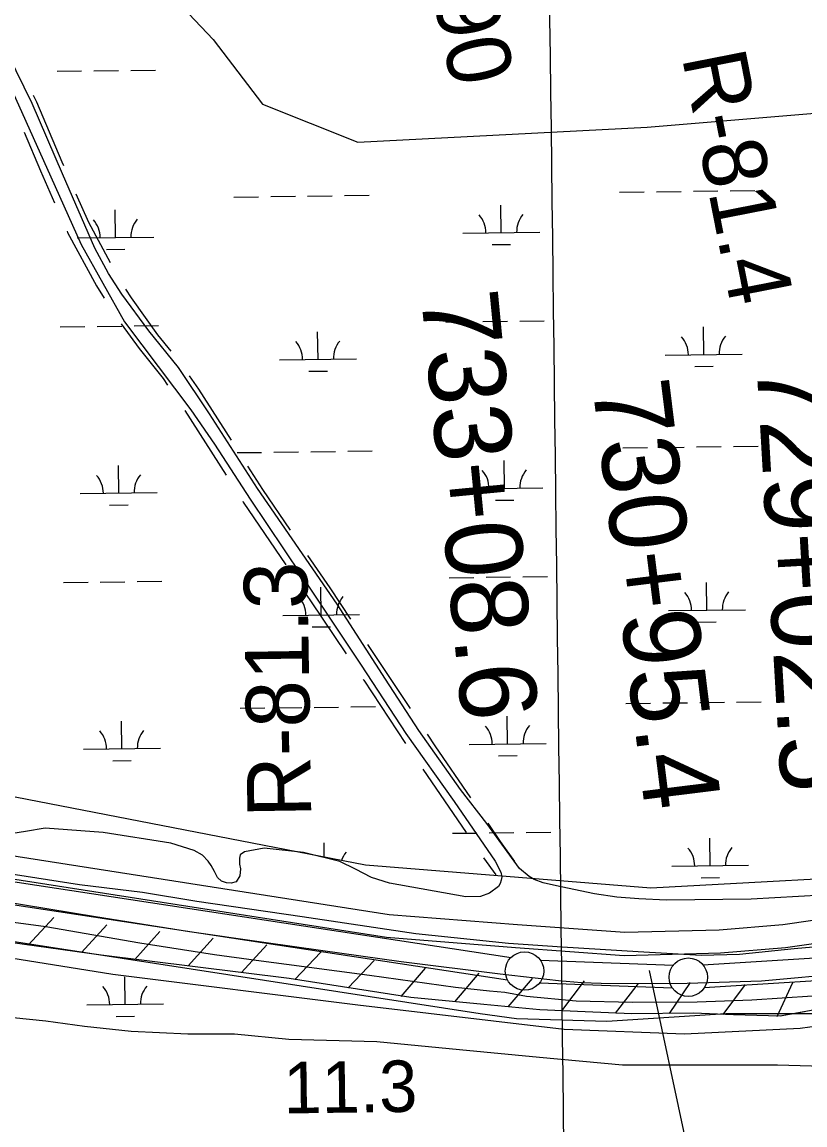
# Model space of a CAD drawing. Extents: x 3715084 to 3753216, y 488173 to 513963.
# Drawn here: x 3729121 to 3730139, y 501088 to 502523 of the extents above; entities that cross this region are included whole.
import ezdxf

# ---------------------------------------------------------------- set-up
doc = ezdxf.new("R2010")
doc.units = 0
for name, color, linetype in [('V-FLOD-BASE', 7, 'Continuous'), ('V-GRID-MAJR', 7, 'Continuous'), ('V-LEVE-TOET', 7, 'Continuous'), ('V-RIVR-RANG', 7, 'Continuous'), ('V-RIVR-RANG-IDEN', 7, 'Continuous'), ('V-ROAD-CNTR', 7, 'Continuous'), ('V-RRAP-FSHR', 7, 'Continuous'), ('V-SITE-VEGE', 7, 'Continuous'), ('V-SURV-IDEN', 7, 'Continuous'), ('V-SURV-LINE', 7, 'Continuous'), ('V-WETL-SWMP', 7, 'Continuous')]:
    doc.layers.add(name, color=color, linetype=linetype)

msp = doc.modelspace()

# ---------------------------------------------------------------- linework, layer by layer
at = {"layer": 'V-FLOD-BASE'}
msp.add_lwpolyline([(3728101.8570000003, 501532.90400000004), (3728267.9250000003, 501507.679), (3728417.988, 501485.28), (3728525.819, 501467.973), (3728627.609, 501453.266), (3728731.631, 501437.386), (3728842.612, 501418.911), (3728945.323, 501403.42), (3729092.378, 501379.042), (3729216.214, 501358.908), (3729338.343, 501339.293), (3729435.279, 501325.61600000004), (3729508.865, 501315.132), (3729613.8030000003, 501300.30700000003), (3729742.866, 501284.386), (3729818.546, 501275.483), (3729848.7090000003, 501272.97000000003), (3729874.147, 501271.88300000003), (3729921.4760000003, 501271.53), (3729985.978, 501272.026), (3730082.981, 501275.264), (3730197.006, 501285.379)], dxfattribs=at)
at = {"layer": 'V-GRID-MAJR'}
msp.add_spline([(3729916.433, 493722.87), (3729841.541, 499780.245), (3729766.611, 505840.705), (3729691.682, 511901.17600000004), (3729691.644, 511904.24700000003)], degree=3, dxfattribs=at)
at = {"layer": 'V-LEVE-TOET'}
for points in [[(3728035.076, 501579.658), (3728225.339, 501552.42600000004), (3728426.043, 501520.704), (3728505.335, 501509.389), (3728525.404, 501506.905), (3728559.646, 501499.753), (3728685.186, 501479.757), (3728858.951, 501446.759), (3729007.306, 501425.864), (3729112.364, 501413.461), (3729195.597, 501400.391), (3729277.245, 501390.659), (3729348.2800000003, 501378.919), (3729485.029, 501358.96400000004), (3729632.9930000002, 501336.884), (3729753.786, 501324.148), (3729823.418, 501319.288), (3729922.359, 501313.156), (3730004.182, 501308.734), (3730053.932, 501309.898), (3730125.293, 501317.039), (3730234.007, 501326.874)], [(3729050.582, 501359.306), (3729151.455, 501345.906), (3729273.86, 501324.455), (3729371.066, 501309.599), (3729425.11, 501302.06), (3729487.812, 501293.764), (3729572.681, 501282.403), (3729684.707, 501266.945), (3729728.909, 501261.993), (3729748.711, 501260.492), (3729776.92, 501255.218), (3729841.711, 501248.898), (3729915.137, 501247.458), (3729998.917, 501247.76300000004), (3730070.362, 501250.514), (3730149.271, 501255.51900000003)]]:
    msp.add_lwpolyline(points, dxfattribs=at)
at = {"layer": 'V-RIVR-RANG'}
msp.add_line((3729936.8287999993, 501288.7174000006), (3730061.664, 500701.8476000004), dxfattribs=at)
at = {"layer": 'V-ROAD-CNTR'}
for p, q in [((3729332.497770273, 502017.3059776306), (3729386.2603967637, 501932.98786953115)), ((3729642.072134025, 501550.70621169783), (3729698.442015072, 501468.1084339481)), ((3729721.091633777, 501435.14045686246), (3729737.008350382, 501412.9557906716))]:
    msp.add_line(p, q, dxfattribs=at)
for points in [[(3729135.065865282, 502427.7652765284), (3729139.284353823, 502418.87586549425), (3729172.3423357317, 502341.00461566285), (3729174.5735020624, 502335.9139316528)], [(3729123.4979500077, 502379.29019478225), (3729144.7956642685, 502329.1213843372), (3729163.058394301, 502287.45269004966)], [(3729190.630779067, 502299.27841511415), (3729206.999017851, 502262.23249178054), (3729235.227540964, 502209.8564943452)], [(3729179.223828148, 502250.8648510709), (3729180.032982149, 502249.03350821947), (3729217.596071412, 502179.33789364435), (3729227.4856427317, 502163.321281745)], [(3729255.3451499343, 502175.30351094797), (3729262.4907595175, 502163.73087025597), (3729296.7832747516, 502115.9733622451), (3729314.079197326, 502094.45888147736)], [(3729249.711292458, 502130.09349961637), (3729272.8907252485, 502097.81263775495), (3729304.0795688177, 502059.0166861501), (3729310.073964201, 502050.4196821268)], [(3729338.179234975, 502062.56342717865), (3729350.3493150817, 502045.1094187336), (3729392.6720825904, 501978.7329055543)], [(3729414.1771332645, 501945.0056621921), (3729433.5695541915, 501914.59174176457), (3729469.5963714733, 501861.7802688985)], [(3729407.76544736, 501899.2606262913), (3729408.5244458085, 501898.07025823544), (3729464.0827990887, 501816.6276360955)], [(3729492.1379453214, 501828.73672507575), (3729520.9823440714, 501786.4539119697), (3729548.1180512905, 501745.8764048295)], [(3729486.624372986, 501783.5840922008), (3729496.121655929, 501769.66208803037), (3729542.3415671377, 501700.5469268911)], [(3729570.353306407, 501712.62681173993), (3729590.141560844, 501683.03635259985), (3729625.700537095, 501629.3424037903)], [(3729564.5768209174, 501667.2973358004), (3729565.166439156, 501666.41564740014), (3729619.7948608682, 501583.9268924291)], [(3729647.786165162, 501595.9931708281), (3729657.6225357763, 501581.1402803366), (3729703.950138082, 501513.25727388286)], [(3728474.6570116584, 501538.26089735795), (3728912.663135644, 501468.68203651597), (3729598.3777642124, 501361.644250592), (3729765.140430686, 501348.3032772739), (3729904.9471510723, 501338.317297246), (3730027.6799056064, 501341.634290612), (3730110.469740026, 501348.258277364), (3730149.535661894, 501354.0752657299), (3730214.2135325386, 501361.63625060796)], [(3728469.95102107, 501508.632956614), (3728907.997144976, 501439.048095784), (3729594.86377124, 501331.83031022), (3729762.876435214, 501318.38933710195), (3729904.281152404, 501308.28935730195), (3730029.281902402, 501311.66635054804), (3730113.879733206, 501318.43433701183), (3730153.48765399, 501324.3333252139), (3730217.69752557, 501331.83831020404)], [(3729726.4980901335, 501480.21816332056), (3729742.593367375, 501456.63404166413), (3729761.3836496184, 501430.44420932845)]]:
    msp.add_lwpolyline(points, dxfattribs=at)
at = {"layer": 'V-RRAP-FSHR'}
for p, q in [((3729128.58, 501321.739), (3729161.853, 501357.48)), ((3729197.9080000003, 501312.056), (3729231.18, 501347.797)), ((3729267.325, 501303.059), (3729300.029, 501339.32)), ((3729336.796, 501294.47000000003), (3729369.5, 501330.732)), ((3729406.267, 501285.882), (3729438.971, 501322.143)), ((3729475.705, 501277.053), (3729509.5670000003, 501312.235)), ((3729544.861, 501266.216), (3729578.723, 501301.398)), ((3729613.923, 501254.637), (3729645.659, 501291.748)), ((3729683.596, 501247.882), (3729715.333, 501284.993)), ((3729753.275, 501241.189), (3729784.941, 501278.36)), ((3729823.068, 501236.136), (3729852.667, 501274.973)), ((3729893.003, 501233.136), (3729922.773, 501271.842)), ((3729962.9790000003, 501232.696), (3729990.5640000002, 501272.989)), ((3730032.941, 501231.326), (3730062.043, 501270.537)), ((3730102.9760000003, 501228.579), (3730123.483, 501272.89400000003))]:
    msp.add_line(p, q, dxfattribs=at)
for points in [[(3730161.524, 501239.07800000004), (3730106.904, 501229.283), (3730046.286, 501230.957), (3729994.281, 501233.026), (3729914.274, 501232.183), (3729853.183, 501234.92), (3729794.159, 501237.304), (3729721.532, 501244.205), (3729626.6070000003, 501253.407), (3729468.301, 501278.213), (3729223.757, 501308.445), (3728811.901, 501365.971), (3728548.752, 501405.373)], [(3730138.552, 501234.958), (3730106.904, 501229.283), (3730046.286, 501230.957), (3729994.281, 501233.026), (3729914.274, 501232.183), (3729853.183, 501234.92), (3729794.159, 501237.304), (3729721.532, 501244.205), (3729626.6070000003, 501253.407), (3729468.301, 501278.213), (3729223.757, 501308.445), (3728974.276, 501343.291)]]:
    msp.add_lwpolyline(points, dxfattribs=at)
at = {"layer": 'V-SITE-VEGE'}
for points in [[(3730192.551, 501388.17), (3730069.381, 501381.612), (3729959.002, 501380.226), (3729923.319, 501381.873), (3729894.3340000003, 501384.132), (3729865.541, 501388.166), (3729830.231, 501395.72500000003), (3729816.225, 501398.631), (3729798.67, 501402.707), (3729787.025, 501406.805), (3729780.307, 501410.723), (3729768.048, 501421.125), (3729725.458, 501479.71), (3729690.998, 501524.13300000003), (3729637.105, 501600.81), (3729593.4990000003, 501667.472), (3729530.8570000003, 501765.408), (3729426.827, 501916.016), (3729364.778, 502013.167), (3729324.1520000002, 502073.335), (3729285.74, 502120.897), (3729250.4820000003, 502168.667), (3729233.233, 502195.412), (3729215.375, 502228.463), (3729173.233, 502325.487), (3729133.6780000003, 502416.803), (3729081.255, 502523.053)], [(3729102.561, 502445.092), (3729157.9390000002, 502321.259), (3729197.436, 502233.202), (3729253.912, 502132.606), (3729276.661, 502102.566), (3729340.166, 502018.139), (3729371.041, 501973.364), (3729417.369, 501901.868), (3729483.683, 501802.882), (3729561.876, 501685.827), (3729620.08, 501596.851), (3729683.007, 501508.683), (3729736.251, 501430.715), (3729743.5870000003, 501416.568), (3729744.789, 501410.471), (3729744.213, 501406.135), (3729742.6550000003, 501401.798), (3729740.502, 501398.05), (3729728.722, 501389.344), (3729717.123, 501384.969), (3729698.029, 501384.31200000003), (3729598.736, 501402.064), (3729575.477, 501409.658), (3729554.37, 501420.604), (3729534.058, 501430.375), (3729486.7660000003, 501442.016), (3729435.752, 501447.935), (3729409.98, 501443.11600000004), (3729404.6780000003, 501439.159), (3729403.512, 501434.824), (3729403.541, 501426.949), (3729404.7430000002, 501420.85000000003), (3729404.186, 501411.59500000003), (3729399.097, 501403.89900000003), (3729392.6070000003, 501402.103), (3729386.698, 501402.47500000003), (3729380.194, 501404.618), (3729374.859, 501409.521), (3729370.894, 501417.577), (3729366.73, 501425.042), (3729362.773, 501430.738), (3729355.458, 501438.784)], [(3729355.458, 501438.784), (3729344.806, 501444.849), (3729314.256, 501454.18700000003), (3729226.397, 501468.044), (3729150.582, 501473.674), (3729125.001, 501469.646), (3729094.698, 501464.614), (3729070.876, 501464.919), (3729053.7260000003, 501470.56700000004), (3729046.433, 501473.297), (3729000.4820000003, 501494.787), (3728941.555, 501511.308), (3728885.1920000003, 501526.658), (3728795.512, 501554.683), (3728766.148, 501562.451), (3728750.589, 501564.56), (3728739.95, 501566.293), (3728731.6720000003, 501569.01900000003), (3728718.8540000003, 501575.077)], [(3728139.159, 501273.31200000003), (3728207.265, 501368.634), (3728225.255, 501389.614), (3728260.802, 501418.268), (3728285.015, 501426.91000000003), (3728312.111, 501427.48600000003), (3728364.433, 501418.642), (3728515.207, 501395.897), (3728918.542, 501335.086), (3729238.65, 501283.958), (3729557.77, 501243.75800000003), (3729825.992, 501212.407), (3729982.41, 501206.316), (3730133.075, 501213.521), (3730246.1580000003, 501229.143)]]:
    msp.add_lwpolyline(points, dxfattribs=at)
at = {"layer": 'V-SURV-LINE'}
for points in [[(3728593.618966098, 501482.76035879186), (3729756.954803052, 501305.68285678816)], [(3729752.4540938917, 501276.0223812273), (3728589.1182569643, 501453.0998832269)], [(3729794.995389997, 501302.08607701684), (3729968.078350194, 501295.59220168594)], [(3730006.4979883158, 501296.0778790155), (3730159.0367881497, 501305.6637474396)], [(3729966.9461499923, 501265.6135729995), (3729793.8631898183, 501272.10744832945)], [(3730160.900381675, 501275.7216809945), (3730008.3615818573, 501266.1358125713)]]:
    msp.add_lwpolyline(points, dxfattribs=at)
for centre in [(3729774.45594, 501287.84613999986), (3729987.4856, 501279.85351)]:
    msp.add_circle(centre, 25, dxfattribs=at)
at = {"layer": 'V-WETL-SWMP'}
for p, q in [((3729166.200790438, 502458.750369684), (3729198.1982918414, 502459.1502495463)), ((3729214.1970425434, 502459.3501894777), (3729246.1945439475, 502459.75006933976)), ((3729262.193294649, 502459.95000927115), (3729294.190796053, 502460.34988913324)), ((3730042.121192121, 502303.1829393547), (3730074.118693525, 502303.582819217)), ((3729396.263625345, 502295.1115142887), (3729428.2611267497, 502295.51139415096)), ((3729444.2598774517, 502295.7113340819), (3729476.2573788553, 502296.11121394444)), ((3729492.2561295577, 502296.3111538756), (3729524.2536309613, 502296.7110337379)), ((3729540.2523816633, 502296.9109736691), (3729572.2498830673, 502297.31085353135)), ((3729898.1324358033, 502301.3834799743), (3729930.1299372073, 502301.7833598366)), ((3729946.1286879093, 502301.9832997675), (3729978.126189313, 502302.38317963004)), ((3729994.124940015, 502302.5831195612), (3730026.122441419, 502302.9829994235)), ((3729242.3177805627, 502242.4416566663), (3729241.8679157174, 502278.4388457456)), ((3729744.1865910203, 502248.7136223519), (3729743.7367261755, 502284.71081143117)), ((3729694.190495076, 502248.0888100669), (3729794.182686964, 502249.3384346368)), ((3729192.3216846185, 502241.81684438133), (3729292.313876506, 502243.06646895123)), ((3729732.380357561, 502233.13387227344), (3729756.378483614, 502233.4337821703)), ((3729230.511547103, 502226.86190658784), (3729254.509673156, 502227.1618164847)), ((3729672.2267894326, 502132.37331100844), (3729704.224290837, 502132.77319087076)), ((3729720.2230415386, 502132.97313080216), (3729752.2205429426, 502133.37301066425)), ((3729768.2192936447, 502133.57295059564), (3729800.2167950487, 502133.9728304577)), ((3729170.357978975, 502126.10134532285), (3729202.355480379, 502126.5012251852)), ((3729218.354231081, 502126.70116511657), (3729250.351732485, 502127.10104497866)), ((3729266.350483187, 502127.30098491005), (3729298.3479845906, 502127.7008647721)), ((3729505.756034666, 502083.85926352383), (3729505.306169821, 502119.8564526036)), ((3730007.6248451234, 502090.1312292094), (3730007.174980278, 502126.1284182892)), ((3729957.62874918, 502089.5064169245), (3730057.620941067, 502090.75604149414)), ((3729455.7599387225, 502083.2344512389), (3729555.7521306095, 502084.48407580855)), ((3729995.818611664, 502074.551479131), (3730019.816737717, 502074.85138902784)), ((3729493.9498012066, 502068.2795134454), (3729517.9479272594, 502068.57942334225)), ((3729400.4208138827, 501962.46248992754), (3729432.4183152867, 501962.86236978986)), ((3729448.4170659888, 501963.0623097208), (3729480.4145673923, 501963.46218958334)), ((3729496.413318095, 501963.66212951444), (3729528.410819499, 501964.06200937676)), ((3729544.409570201, 501964.2619493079), (3729576.407071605, 501964.66182917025)), ((3729902.289624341, 501968.7344556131), (3729934.287125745, 501969.13433547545)), ((3729950.285876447, 501969.3342754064), (3729982.2833778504, 501969.73415526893)), ((3729998.2821285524, 501969.9340952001), (3730030.2796299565, 501970.33397506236)), ((3730046.278380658, 501970.5339149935), (3730078.275882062, 501970.93379485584)), ((3729246.4749690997, 501909.7926323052), (3729246.025104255, 501945.7898213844)), ((3729748.3437795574, 501916.0645979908), (3729747.8939147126, 501952.06178707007)), ((3729698.3476836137, 501915.4397857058), (3729798.3398755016, 501916.6894102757)), ((3729196.4788731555, 501909.16782002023), (3729296.4710650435, 501910.41744459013)), ((3729234.6687356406, 501894.21288222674), (3729258.6668616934, 501894.51279212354)), ((3729736.537546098, 501900.48484791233), (3729760.535672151, 501900.7847578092)), ((3729772.376482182, 501800.92392623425), (3729804.373983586, 501801.32380609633)), ((3729174.5151675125, 501793.4523209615), (3729206.512668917, 501793.8522008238)), ((3729222.5114196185, 501794.0521407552), (3729254.5089210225, 501794.45202061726)), ((3729270.5076717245, 501794.65196054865), (3729302.505173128, 501795.05184041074)), ((3729509.9132232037, 501751.21023916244), (3729509.4633583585, 501787.2074282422)), ((3729676.38397797, 501799.7242866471), (3729708.3814793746, 501800.1241665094)), ((3729724.3802300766, 501800.3241064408), (3729756.37773148, 501800.72398630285)), ((3730011.782033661, 501757.4822048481), (3730011.3321688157, 501793.47939392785)), ((3729961.7859377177, 501756.85739256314), (3730061.778129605, 501758.10701713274)), ((3729459.9171272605, 501750.5854268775), (3729559.909319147, 501751.83505144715)), ((3729498.106989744, 501735.630489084), (3729522.105115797, 501735.93039898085)), ((3729999.9758002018, 501741.90245476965), (3730023.973926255, 501742.20236466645)), ((3729404.5780024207, 501629.81346556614), (3729436.5755038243, 501630.21334542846)), ((3729452.5742545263, 501630.4132853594), (3729484.57175593, 501630.81316522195)), ((3729500.5705066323, 501631.0131051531), (3729532.5680080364, 501631.4129850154)), ((3729548.5667587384, 501631.61292494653), (3729580.5642601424, 501632.01280480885)), ((3729906.4468128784, 501636.0854312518), (3729938.4443142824, 501636.48531111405)), ((3729954.4430649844, 501636.685251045), (3729986.4405663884, 501637.08513090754)), ((3730002.43931709, 501637.2850708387), (3730034.436818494, 501637.684950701)), ((3730050.435569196, 501637.8848906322), (3730082.4330705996, 501638.28477049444)), ((3729752.500968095, 501583.4155736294), (3729752.05110325, 501619.4127627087)), ((3729250.6321576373, 501577.1436079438), (3729250.1822927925, 501613.1407970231)), ((3729200.636061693, 501576.51879565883), (3729300.628253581, 501577.76842022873)), ((3729702.5048721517, 501582.7907613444), (3729802.497064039, 501584.0403859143)), ((3729238.825924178, 501561.56385786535), (3729262.824050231, 501561.8637677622)), ((3729740.6947346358, 501567.83582355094), (3729764.6928606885, 501568.1357334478)), ((3729680.5411665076, 501467.07526228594), (3729712.5386679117, 501467.47514214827)), ((3729728.5374186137, 501467.67508207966), (3729760.5349200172, 501468.07496194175)), ((3729776.5336707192, 501468.27490187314), (3729808.5311721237, 501468.6747817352)), ((3730015.9392221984, 501424.8331804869), (3730015.489357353, 501460.8303695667)), ((3729513.853983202, 501435.8793473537), (3729513.6205468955, 501454.5584038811)), ((3729965.943126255, 501424.208368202), (3730065.935318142, 501425.45799277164)), ((3730004.1329887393, 501409.2534304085), (3730028.131114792, 501409.55334030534)), ((3729254.7893461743, 501244.4945835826), (3729254.3394813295, 501280.4917726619)), ((3729204.793250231, 501243.86977129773), (3729304.7854421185, 501245.1193958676)), ((3729242.983112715, 501228.9148335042), (3729266.981238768, 501229.21474340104))]:
    msp.add_line(p, q, dxfattribs=at)
for points in [[(3729250.465, 502599.092), (3729290.08, 502584.23600000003), (3729369.31, 502500.055), (3729433.684, 502415.873), (3729557.481, 502366.355), (3729933.822, 502386.162)], [(3730305.211, 501415.597), (3729938.774, 501395.79000000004), (3729567.384, 501425.501), (3729082.102, 501519.587), (3728869.1720000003, 501579.009), (3728725.568, 501628.527), (3728710.713, 501673.094), (3728720.616, 501712.70900000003), (3728715.664, 501752.324), (3728710.713, 501786.987), (3728666.146, 501856.313), (3728611.6750000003, 501945.446), (3728562.157, 502029.628), (3728477.975, 502178.184), (3728458.168, 502252.462), (3728393.793, 502331.69200000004), (3728344.275, 502415.873), (3728388.842, 502475.29600000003), (3728482.927, 502509.95900000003), (3728567.109, 502519.862), (3728631.483, 502524.814)], [(3729933.822, 502386.162), (3730468.623, 502430.729)], [(3728175.903, 501363.844), (3728192.724, 501400.851), (3728216.274, 501431.129), (3728239.824, 501454.679), (3728286.924, 501454.679), (3729107.81, 501326.836), (3729716.745, 501232.637), (3729763.845, 501225.908), (3729881.595, 501222.544), (3730036.352, 501232.637), (3730160.8310000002, 501232.637)], [(3730221.3880000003, 501161.987), (3730103.6380000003, 501165.351), (3730006.074, 501165.351), (3729901.781, 501165.351), (3729794.1240000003, 501175.444), (3729689.8310000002, 501185.537), (3729582.174, 501195.629), (3729467.788, 501198.994), (3729397.1380000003, 501205.722), (3729336.5810000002, 501205.722), (3729262.5670000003, 501209.087), (3729202.0100000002, 501215.815), (3729151.546, 501222.544), (3729087.6240000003, 501229.272)]]:
    msp.add_lwpolyline(points, dxfattribs=at)
for centre, radius, start, end in [((3729187.0732246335, 502242.22609347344), 35.24628790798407, 359.94418071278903, 41.48783904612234), ((3729297.5504699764, 502243.6067520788), 35.246287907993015, 139.9441777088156, 181.48783604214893), ((3729688.9420350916, 502248.498059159), 35.24628790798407, 359.94418071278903, 41.48783904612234), ((3729799.4192804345, 502249.8787177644), 35.246287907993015, 139.9441777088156, 181.48783604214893), ((3729450.5114787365, 502083.6437003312), 35.24628790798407, 359.94418071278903, 41.48783904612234), ((3729560.9887240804, 502085.0243589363), 35.246287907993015, 139.9441777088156, 181.48783604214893), ((3729952.380289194, 502089.9156660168), 35.24628790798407, 359.94418071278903, 41.48783904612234), ((3730062.857534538, 502091.29632462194), 35.246287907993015, 139.9441777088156, 181.48783604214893), ((3729191.230413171, 501909.57706911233), 35.24628790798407, 359.94418071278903, 41.48783904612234), ((3729301.707658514, 501910.95772771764), 35.246287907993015, 139.9441777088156, 181.48783604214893), ((3729693.0992236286, 501915.8490347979), 35.24628790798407, 359.94418071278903, 41.48783904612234), ((3729803.5764689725, 501917.22969340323), 35.246287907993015, 139.9441777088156, 181.48783604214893), ((3729454.668667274, 501750.9946759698), 35.24628790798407, 359.94418071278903, 41.48783904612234), ((3729565.145912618, 501752.37533457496), 35.246287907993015, 139.9441777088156, 181.48783604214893), ((3729956.5374777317, 501757.2666416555), 35.24628790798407, 359.94418071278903, 41.48783904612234), ((3730067.0147230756, 501758.64730026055), 35.246287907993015, 139.9441777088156, 181.48783604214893), ((3729195.3876017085, 501576.92804475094), 35.24628790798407, 359.94418071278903, 41.48783904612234), ((3729305.864847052, 501578.30870335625), 35.246287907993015, 139.9441777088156, 181.48783604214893), ((3729697.256412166, 501583.2000104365), 35.24628790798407, 359.94418071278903, 41.48783904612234), ((3729807.73365751, 501584.5806690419), 35.246287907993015, 139.9441777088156, 181.48783604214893), ((3729569.3031011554, 501419.7263102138), 35.246287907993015, 139.94417770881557, 160.37294897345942), ((3729960.6946662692, 501424.6176172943), 35.24628790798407, 359.94418071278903, 41.48783904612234), ((3730071.1719116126, 501425.99827589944), 35.246287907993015, 139.9441777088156, 181.48783604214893), ((3729458.825855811, 501418.3456516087), 35.24628790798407, 40.79718086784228, 41.487839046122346), ((3729199.5447902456, 501244.27902038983), 35.24628790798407, 359.94418071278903, 41.48783904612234), ((3729310.0220355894, 501245.65967899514), 35.246287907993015, 139.9441777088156, 181.48783604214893)]:
    msp.add_arc(centre, radius, start, end, dxfattribs=at)

# ---------------------------------------------------------------- texts
at = {"layer": 'V-RIVR-RANG'}
msp.add_text('11.3', height=66.99999999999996, rotation=0.7683257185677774, dxfattribs=at).set_placement((3729461.0581003, 501102.4833042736))
at = {"layer": 'V-RIVR-RANG-IDEN'}
for s, height, rotation, p in [('D-090', 83, 281.8673257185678, (3729618.6608449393, 502730.8932306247)), ('R-81.4', 82.999998, 281.12457403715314, (3729979.097, 502477.356)), ('R-81.3', 82.999998, 90.90938387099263, (3729497.0506587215, 501487.99575567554))]:
    msp.add_text(s, height=height, rotation=rotation, dxfattribs=at).set_placement(p)
at = {"layer": 'V-SURV-IDEN'}
for s, height, rotation, p in [('733+08.6', 99.99999999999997, 275.5174049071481, (3729639.5769846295, 502169.15691413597)), ('729+02.5', 99.99999999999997, 273.3333960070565, (3730076.135395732, 502079.0665036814)), ('730+95.4', 100.00000000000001, 277.07314735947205, (3729862.38300471, 502051.53164591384))]:
    msp.add_text(s, height=height, rotation=rotation, dxfattribs=at).set_placement(p)

doc.saveas('drawing.dxf')
